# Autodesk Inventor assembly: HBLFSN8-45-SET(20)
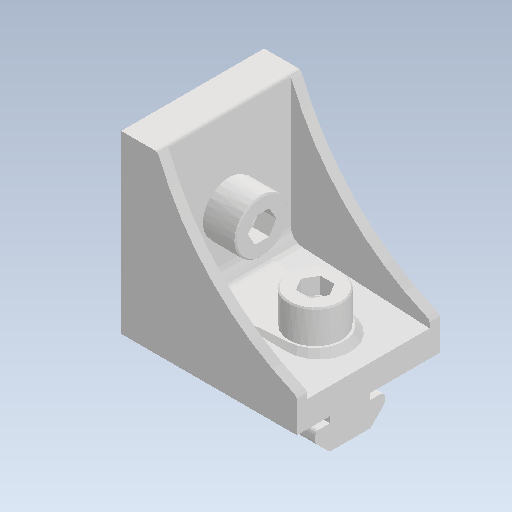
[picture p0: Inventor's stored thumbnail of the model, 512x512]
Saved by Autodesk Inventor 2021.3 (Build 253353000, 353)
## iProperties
Created: 2022-02
Part Number: HBLFSN8-45-SET(20)
Document SubType Name: Assembly
Designer: kengo
Author: kengo
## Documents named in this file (4)
- C:\Users\kengo\Documents\S2S_frame\SDC345\frame_misumi_ver12\HBLFSN8-45-SET(20).iam
- C:\Users\kengo\Documents\S2S_frame\SDC345\frame_misumi_ver12\HBLFSN8-45.ipt
- C:\Users\kengo\Documents\S2S_frame\SDC345\frame_misumi_ver12\HNTT8-8.ipt
- C:\Users\kengo\Documents\S2S_frame\SDC345\frame_misumi_ver12\CBM8-20.ipt
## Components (5 placed, 3 different names)
1. HBLFSN8-45
2. HNTT8-8
3. CBM8-20
4. HNTT8-8:1
5. CBM8-20:1
